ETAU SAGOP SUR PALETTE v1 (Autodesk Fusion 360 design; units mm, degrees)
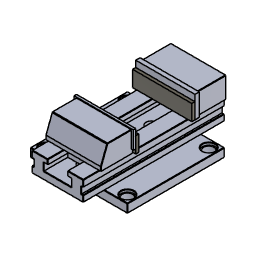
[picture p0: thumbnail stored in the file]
parameter "Ouverture" = 150
parameter "epaisseurcale" = 8
parameter "hauteurcale" = 40
base_feature "Base Feature1"
base_feature "Base Feature1"
base_feature "Base Feature1"
base_feature "Base Feature1"
as_built_joint "As-built1"
sketch "Sketch1" plane through (-65, 179, 42) normal (1, 0, 0) x axis (0, 1, 0)
  line L1 (-178, 8) -> (94, 8)
  line L2 (94, 8) -> (94, 64)
  line L3 (-6, 19) -> (-6, 64)
  line L4 (86, 48) -> (94, 48)
  line L5 (86, 8) -> (86, 48)
  line L6 (94, 8) -> (86, 8)
  line L7 (94, 48) -> (94, 8)
  line L8 (-6, 48) -> (2, 48)
  line L9 (-6, 8) -> (-6, 48)
  line L10 (2, 8) -> (-6, 8)
  line L11 (2, 48) -> (2, 8)
  point P8 (94, 48)
  point P9 (86, 48)
  point P12 (2, 48)
  point P13 (-6, 48)
  point P15 (2, 8)
  point P10 (86, 8)
  horizontal L4
  vertical L5
  horizontal L6
  vertical L7
  horizontal L8
  vertical L9
  horizontal L10
  vertical L11
  collinear L2 L7
  collinear L1 L6
  collinear L3 L9
  collinear L1 L10
  dimension "d4" distance P8 P9 = 8 (= "epaisseurcale")
  dimension "d5" distance P12 P13 = 8 (= "epaisseurcale")
  dimension "d6" distance P12 P15 = 40 (= "hauteurcale")
  dimension "d7" distance P9 P10 = 40 (= "hauteurcale")
extrude "Extrude1" new body sketch "Sketch1" profile of L4 L5 L6 L7 distance 150
extrude "Extrude1" new body sketch "Sketch1" profile of L8 L9 L10 L11 distance 150
joint "Assemble1" alignOffsetX 0 alignOffsetY 0 alignOffsetZ 150 (= "Ouverture")
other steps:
create_component "CreateComponent1"
create_component "CreateComponent2"
create_component "CreateComponent1"
create_component "CreateComponent2"
joint_origin "JointOrigin1" OffsetX 0 OffsetY 0 OffsetZ 0
joint_origin "JointOrigin1" OffsetX 0 OffsetY 0 OffsetZ 0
